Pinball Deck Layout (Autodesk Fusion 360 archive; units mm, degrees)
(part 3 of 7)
sketch "Posts Top" plane through (0, 0, 0) normal (0, 0, 1) x axis (1, 0, 0)
  line L1 (118.1698, 344.446) -> (150.6579, 255.1857)
  line L2 (143.7676, 248.9817) -> (113.9231, 263.5378)
  line L3 (108.8986, 346.3925) -> (111.7612, 347.4344)
  line L4 (106.0607, 276.0245) -> (105.6088, 341.6596)
  line L5 (250, 300) -> (250, 150)
  line L6 (250, 125) -> (250, 350)
  line L7 (391.1014, 346.3925) -> (388.2388, 347.4344)
  line L8 (393.9393, 276.0245) -> (394.3912, 341.6596)
  line L9 (381.8302, 344.446) -> (349.3421, 255.1857)
  line L10 (356.2324, 248.9817) -> (386.0769, 263.5378)
  circle C1 centre (112.8737, 341.4542) radius 2.25
  arc A1 centre (120.0603, 276.1209) radius 14 clockwise from (113.9231, 263.5378) to (106.0607, 276.0245)
  arc A2 centre (145.9594, 253.4756) radius 5 clockwise from (150.6579, 255.1857) to (143.7676, 248.9817)
  circle C2 centre (143.9975, 255.9422) radius 4
  circle C3 centre (113.492, 272.5077) radius 4
  circle C4 centre (113.492, 272.5077) radius 2.25
  circle C5 centre (112.8737, 341.4542) radius 4
  arc A3 centre (110.6087, 341.694) radius 5 clockwise from (105.6088, 341.6596) to (108.8986, 346.3925)
  arc A4 centre (113.4713, 342.7359) radius 5 clockwise from (111.7612, 347.4344) to (118.1698, 344.446)
  circle C6 centre (143.9975, 255.9422) radius 2.25
  circle C7 centre (386.508, 272.5077) radius 4
  arc A5 centre (389.3913, 341.694) radius 5 clockwise from (391.1014, 346.3925) to (394.3912, 341.6596)
  arc A6 centre (379.9397, 276.1209) radius 14 clockwise from (393.9393, 276.0245) to (386.0769, 263.5378)
  arc A7 centre (386.5287, 342.7359) radius 5 clockwise from (381.8302, 344.446) to (388.2388, 347.4344)
  circle C8 centre (387.1263, 341.4542) radius 4
  circle C9 centre (386.508, 272.5077) radius 2.25
  circle C10 centre (356.0025, 255.9422) radius 4
  circle C11 centre (387.1263, 341.4542) radius 2.25
  circle C12 centre (356.0025, 255.9422) radius 2.25
  arc A8 centre (354.0406, 253.4756) radius 5 clockwise from (356.2324, 248.9817) to (349.3421, 255.1857)
  point P3 (143.7676, 248.9817)
  point P25 (356.2324, 248.9817)
  point P5 (106.0607, 276.0245)
  point P26 (393.9393, 276.0245)
  point P6 (113.9231, 263.5378)
  point P28 (386.0769, 263.5378)
  point P11 (108.8986, 346.3925)
  point P29 (391.1014, 346.3925)
  point P12 (105.6088, 341.6596)
  point P27 (394.3912, 341.6596)
  point P16 (118.1698, 344.446)
  point P35 (381.8302, 344.446)
  point P18 (150.6579, 255.1857)
  point P40 (349.3421, 255.1857)
  point P19 (111.7612, 347.4344)
  point P37 (388.2388, 347.4344)
  perpendicular L1 L3
  tangent L1 A4
  tangent L3 A4
  tangent L3 A3
  tangent L4 A3
  concentric C3 C4
  concentric C1 C5
  tangent A1 L4
  tangent A1 L2
  tangent L2 A2
  tangent L1 A2
  parallel L5 L6
  symmetric P3 L6 P25
  symmetric P5 L6 P26
  symmetric P6 L6 P28
  symmetric P11 L6 P29
  symmetric P12 L6 P27
  symmetric P16 L6 P35
  symmetric P18 L6 P40
  symmetric P19 L6 P37
  symmetric C1 L6 C11
  symmetric A1 L6 A6
  symmetric A2 L6 A8
  symmetric C2 L6 C10
  symmetric C3 L6 C7
  symmetric C4 L6 C9
  symmetric C5 L6 C8
  symmetric A3 L6 A5
  symmetric A4 L6 A7
  symmetric C6 L6 C12
  dimension "d449" radius A4 = 5
  dimension "d450" radius A3 = 5
  dimension "d451" diameter C3 = 8
  dimension "d452" diameter C5 = 8
  dimension "d453" diameter C2 = 8
  dimension "d454" radius A1 = 14
  dimension "d455" radius A2 = 5
sketch "Right Launch Alley Wall" plane through (0, 0, 0) normal (0, 0, 1) x axis (1, 0, 0)
  line L1 (465, 200) -> (0.189, 200)
  line L2 (465, 200) -> (475.0152, 200)
  line L3 (465, 400) -> (465, 200.5)
  line L4 (475.0152, 200.5) -> (475.0152, 400)
  line L5 (475.0152, 200.5) -> (465, 200.5)
  line L6 (448.6603, 645) -> (465, 645)
  line L7 (464.7848, 721.9615) -> (443.8666, 651.4215)
  line L8 (475.0152, 400) -> (465, 400)
  line L9 (475, 400.5) -> (475, 423.4891)
  line L10 (465, 400.5) -> (475, 400.5)
  line L11 (465, 400.5) -> (465, 427.4801)
  line L12 (475, 532.1855) -> (465, 532.1855)
  line L13 (475, 531.6855) -> (465, 531.6855)
  line L14 (475, 531.6855) -> (475, 423.4891)
  line L15 (475, 721.9615) -> (475, 532.1855)
  line L16 (465, 531.6855) -> (465, 427.4801)
  line L17 (465, 645) -> (465, 532.1855)
  line L18 (464.7848, 721.9615) -> (475, 721.9615)
  line L19 (465, 723) -> (475, 723)
  line L20 (465, 750) -> (465, 723)
  line L21 (475, 750) -> (475, 723)
  line L22 (416.1118, 853.4419) -> (416.0548, 853.3004)
  line L23 (412.9292, 846.5912) -> (419.3573, 841.731)
  line L24 (419.0143, 854.221) -> (412.9292, 846.5912)
  circle C1 centre (470.0076, 235) radius 2.25
  circle C2 centre (470.0076, 235) radius 4
  circle C3 centre (470.0076, 350) radius 4
  circle C4 centre (470.0076, 350) radius 2.25
  circle C5 centre (470, 435) radius 4
  circle C6 centre (470, 435) radius 1.9
  circle C7 centre (470, 716) radius 1.9
  circle C8 centre (470, 716) radius 4
  circle C9 centre (470, 505) radius 1.9
  circle C10 centre (470, 505) radius 4
  circle C11 centre (450, 651) radius 1.9
  circle C12 centre (450, 651) radius 4
  arc A1 centre (448.6603, 650) radius 5 clockwise from (448.6603, 645) to (443.8666, 651.4215)
  circle C13 centre (470, 560) radius 1.9
  circle C14 centre (470, 560) radius 4
  arc A2 centre (350, 750) radius 150 clockwise from (350, 900) to (500, 750)
  arc A3 centre (350, 750) radius 125 clockwise from (419.0143, 854.221) to (475, 750)
  arc A4 centre (350, 750) radius 115 clockwise from (419.3573, 841.731) to (465, 750)
  circle C15 centre (422, 846) radius 1.9
  circle C16 centre (422, 846) radius 4
  circle C17 centre (470, 729) radius 1.9
  circle C18 centre (470, 729) radius 4
  circle C19 centre (450, 515) radius 2.25
  circle C20 centre (450, 515) radius 9
  point P2 (475.0152, 200)
  point P6 (475.0152, 200)
  point P3 (465, 200)
  point P7 (465, 200)
  point P34 (465, 532.1855)
  point P35 (475, 532.1855)
  point P42 (350, 750)
  point P43 (350, 750)
  point P45 (350, 750)
  coincident P2 P6
  coincident P3 P7
  perpendicular L1 L3
  perpendicular L2 L4
  concentric C1 C2
  concentric C3 C4
  perpendicular L4 L5
  vertical L16
  perpendicular L6 L16
  vertical L14
  concentric C5 C6
  concentric C7 C8
  concentric C9 C10
  concentric C11 C12
  tangent L6 A1
  tangent L7 A1
  perpendicular L8 L9
  perpendicular L9 L10
  coincident P34 L16
  perpendicular L12 L16
  coincident P35 L14
  collinear L14 L15
  collinear L16 L17
  concentric C13 C14
  coincident P42 P43
  coincident P42 P45
  perpendicular L15 L18
  horizontal L19
  tangent A4 L20
  tangent A3 L21
  concentric C15 C16
  concentric C17 C18
  tangent A4 L23
  concentric C19 C20
  dimension "d456" diameter C1 = 4.5
  dimension "d457" diameter C2 = 8
  dimension "d458" diameter C4 = 4.5
  dimension "d459" diameter C3 = 8
  dimension "d484" radius A1 = 5
extrude "Extrude76" new body sketch "Right Launch Alley Wall" profile of L2 L3 L4 C2 C3 along normal blind 25 bodies "Right Launch Runway"
extrude "Extrude77" add sketch "Right Launch Alley Wall" profile of C1 C2 C3 C4 along normal blind 4
fillet "Fillet24" radius 1
fillet "Fillet25" radius 2
extrude "Extrude78" new body sketch "Right Launch Alley Wall" profile of L17 L6 L7 L15 C5 C8 C10 C12 A1 along normal blind 25 bodies "Right Launch Runway Top"
extrude "Extrude80" new body sketch "Bottom Runways" along normal blind 25 bodies "Left Middle Runway"
extrude "Extrude81" add sketch "Bottom Runways" along normal blind 5
extrude "Extrude82" new body sketch "Bottom Runways" along normal blind 25 bodies "Left Upper Runway"
work_plane "WorkPlane7"
extrude "Extrude94" new body sketch "Bottom Runways" along normal blind 39
split "Split4"
remove_body "RemoveBody4"
extrude "Extrude95" add sketch "Bottom Runways" blind 3 from offset 36
work_plane "WorkPlane8"
split "Split5" bodies "Top Mid Right Overpass"
split "Split6"
remove_body "RemoveBody5"
extrude "Extrude96" add sketch "Bottom Runways" blind 14 from offset 25
extrude "Extrude97" add sketch "Bottom Runways" blind 14 from offset 25
sketch "Top Left Overpass" plane through (88.7119, 0, 0) normal (-1, 0, 0) x axis (0, -1, 0)
  line L1 (-844, 25) -> (-875, 25)
  line L2 (-844, 39) -> (-844, 25)
  line L3 (-875, 39) -> (-844, 39)
  line L4 (-875, 25) -> (-875, 39)
  line L5 (-875, 28) -> (-875, 25)
  line L6 (-844, 28) -> (-875, 28)
  line L7 (-844, 25) -> (-844, 28)
  line L8 (-875, 25) -> (-844, 25)
  point P2 (-875, 25)
  point P6 (-875, 25)
  point P7 (-875, 28)
  point P8 (-844, 28)
  point P3 (-844, 25)
  point P9 (-844, 25)
  coincident P2 P6
  coincident L4 P7
  coincident L2 P8
  perpendicular L2 L6
  coincident P3 P9
work_plane "WorkPlane9"
split "Split7"
remove_body "RemoveBody6"
extrude "Extrude98" new body sketch "Bottom Runways" along normal blind 28
work_plane "WorkPlane10"
split "Split8" bodies "Top Left Overpass"
remove_body "RemoveBody7"
extrude "Extrude99" cut sketch "Bottom Runways" along normal blind 50 bodies "Top Mid Left Overpass"
remove_body "RemoveBody8"
extrude "Extrude100" add sketch "Bottom Runways" along normal blind 55
extrude "Extrude101" cut sketch "Bottom Runways" along normal blind 60 bodies "Top Mid Right Overpass Ramp (1)"
work_plane "WorkPlane11" AlongDistance -16
split "Split9" bodies "Top Mid Right Overpass Ramp (1)"
remove_body "RemoveBody9"
remove_body "RemoveBody10"
fillet "Fillet36" radius 1.5
fillet "Fillet37" radius 20
extrude "Extrude102" add sketch "Bottom Runways" blind 30 from offset 25
work_plane "WorkPlane12" AlongDistance 15
split "Split10" bodies "Top Mid Right Overpass (1)", "Top Mid Right Overpass (2)"
remove_body "RemoveBody11"
remove_body "RemoveBody12"
split "Split11" bodies "Top Mid Right Overpass Ramp (2) (2)", "Top Mid Right Overpass Ramp (2) (1)"
remove_body "RemoveBody13"
remove_body "RemoveBody14"
extrude "Extrude103" cut sketch "Bottom Runways" along normal blind 60
extrude "Extrude104" add sketch "Bottom Runways" blind 30 from offset 25
split "Split12" bodies "Top Mid Left Overpass (1)", "Top Mid Left Overpass (2)"
remove_body "RemoveBody15"
remove_body "RemoveBody16"
extrude "Extrude105" new body sketch "Top Runways" along normal blind 25 bodies "Top Left Corner and ramp down"
combine "Combine6" bodies "Top Left Corner and ramp down"
extrude "Extrude106" add sketch "Top Runways" along normal blind 43
sketch "Left top corner construction lines" plane through (0.0081, 751.001, 0) normal (0, -1, 0) x axis (1, 0, 0)
  line L1 (96.4919, 0) -> (64.9919, 0)
  line L2 (96.4919, 25) -> (96.4919, 0)
  line L3 (96.4919, 43) -> (96.4919, 25)
  line L4 (64.9919, 43) -> (96.4919, 43)
  line L5 (64.9919, 0.298) -> (64.9919, 43)
  line L6 (64.9919, 0) -> (64.9919, 0.298)
  line L7 (95, 25) -> (64.9919, 25)
  horizontal L7
work_plane "WorkPlane13"
split "Split13" bodies "Top Left Overpass (1)", "Top Left Overpass (2)"
remove_body "RemoveBody17"
remove_body "RemoveBody18"
extrude "Extrude108" new body sketch "Bottom Runways" along normal blind 25 bodies "Left Target Framing"
extrude "Extrude110" add sketch "Bottom Runways" along normal blind 5
extrude "Extrude111" add sketch "Bottom Runways" along normal blind 5
fillet "Fillet49" radius 2
fillet "Fillet50" radius 2
fillet "Fillet51" radius 2
work_plane "WorkPlane14" AlongDistance 0.5
extrude "Extrude115" new body sketch "Bottom Runways" blind 3 from offset 25
fillet "Fillet52" radius 2
extrude "Extrude116" add sketch "Bottom Runways" blind 3 from offset 25 bodies "Left Target Framing"
fillet "Fillet53" radius 1.4
extrude "Extrude117" cut sketch "Bottom Runways" blind 40 from offset 5
extrude "Extrude118" cut sketch "Bottom Runways" blind 40 from offset 5
extrude "Extrude119" cut sketch "Top Runways" along normal blind 60
extrude "Extrude120" cut sketch "Top Runways" blind 60 from offset 5
extrude "Extrude121" cut sketch "Bottom Runways" along normal blind 80
fillet "Fillet55" radius 2
extrude "Extrude123" cut sketch "Bottom Runways" blind 80 from offset 5
extrude "Extrude124" new body sketch "Top Runways" along normal blind 24.8 bodies "Middle Ramp Stand"
extrude "Extrude125" add sketch "Top Runways" profile of L35 L36 L37 L38 L41 L42 L43 L44 L45 L46 along normal blind 51
extrude "Extrude126" add sketch "Top Runways" profile of L33 L34 L35 L36 L37 L38 L39 L40 L45 L46 L47 L48 L49 L50 blind 1.6 from offset 49.4
chamfer "Chamfer11" distance 0.8 distance 0.8
fillet "Fillet56" radius 1.5
extrude "Extrude127" add sketch "Top Runways" blind 9.8 from offset 15
extrude "Extrude128" new body sketch "Top Runways" blind 39 from offset 15
extrude "Extrude129" add sketch "Top Runways" blind 1.5 from offset 52.5
combine "Combine7"
extrude "Extrude130" add sketch "Top Runways" blind 20 from offset 15
chamfer "Chamfer12" distance 0.7
chamfer "Chamfer13" distance 10.3
chamfer "Chamfer14" distance 9 distance 2.7
chamfer "Chamfer15" distance 2.6
fillet "Fillet57" radius 2
extrude "Extrude131" new body sketch "Right Launch Alley Wall" profile of L17 L15 C5 C6 C9 C10 L9 L10 L11 L13 along normal blind 25 bodies "Right Mid Launch Runway"
fillet "Fillet58" radius 2
extrude "Extrude132" cut sketch "Right Launch Alley Wall" profile of C6 C9 along normal blind 40
extrude "Extrude133" cut sketch "Right Launch Alley Wall" profile of C5 C6 C9 C10 blind 40 from offset 5
extrude "Extrude134" cut sketch "Right Launch Alley Wall" profile of C13 along normal blind 40
extrude "Extrude135" cut sketch "Right Launch Alley Wall" profile of C13 C14 blind 40 from offset 5
extrude "Extrude136" add sketch "Right Launch Alley Wall" profile of C7 C8 C11 C12 along normal blind 5
extrude "Extrude137" cut sketch "Top Runways" along normal blind 100
extrude "Extrude138" cut sketch "Top Runways" blind 100 from offset 5
combine "Combine8" bodies "Left Upper Runway"
extrude "Extrude139" add sketch "Bottom Runways" along normal blind 5
extrude "Extrude140" new body sketch "Right Launch Alley Wall" profile of A3 A4 L19 L20 L21 C15 C16 C17 C18 along normal blind 25 bodies "Top Entry Runway"
fillet "Fillet59" radius 2
fillet "Fillet60" radius 3
extrude "Extrude142" cut sketch "Right Launch Alley Wall" profile of C15 C16 C17 C18 along normal blind 30
extrude "Extrude143" add sketch "Right Launch Alley Wall" profile of C15 C16 C17 C18 along normal blind 5
fillet "Fillet61" radius 0.4
extrude "Extrude144" cut sketch "Bottom Runways" along normal blind 80
extrude "Extrude145" add sketch "Bottom Runways" along normal blind 5
work_plane "WorkPlane15" AlongDistance 0.2
sketch "Ball Reload Positioner" plane through (0, 0, 25.2) normal (0, 0, 1) x axis (1, 0, 0)
  line L1 (465, 20) -> (499, 20)
  line L2 (465, 53) -> (465, 20)
  line L3 (465, 53) -> (499, 53)
  line L4 (499, 20) -> (499, 53)
  line L5 (496, 20) -> (496, 53)
  line L6 (475.3, 53) -> (475.3, 20)
  line L7 (478.3, 53) -> (478.3, 20)
  line L8
  line L9 (472, 25) -> (472, 45)
  circle C1 centre (470, 25) radius 1.2
  circle C2 centre (470, 45) radius 1.2
  circle C3 centre (470, 55) radius 1.2
  circle C4 centre (470, 35) radius 1.2
  arc A1 centre (470, 25) radius 2 clockwise from (472, 25) to (468, 25)
  arc A2 centre (470, 45) radius 2 clockwise from (468, 45) to (472, 45)
  circle C5 centre (470, 65) radius 1.2
  perpendicular L1 L2
  vertical L4
  vertical L5
  concentric C1 A1
  concentric C2 A2
  tangent L8 A2
  tangent L9 A1
  dimension "d919" diameter C5 = 2.4
  dimension "d920" diameter C3 = 2.4
  dimension "d921" diameter C2 = 2.4
  dimension "d922" diameter C4 = 2.4
  dimension "d923" diameter C1 = 2.4
extrude "Extrude146" new body sketch "Ball Reload Positioner" profile of L1 L2 L3 L4 L5 L6 L7 A1 A2 L8 L9 along normal blind 4 bodies "Ball Reload Positioner"
extrude "Extrude147" add sketch "Ball Reload Positioner" profile of L1 L3 L4 L5 L6 L7 against normal blind 20
fillet "Fillet62" radius 1
fillet "Fillet63" radius 1
extrude "Extrude148" cut sketch "Ball Reload Positioner" profile of C1 C2 C3 C4 C5 against normal blind 10
extrude "Extrude149" add sketch "Bottom Runways" blind 2 from offset 3.1
fillet "Fillet64" radius 0.8
fillet "Fillet65" radius 5
extrude "Extrude150" cut sketch "Top Runways" profile of L33 L34 L35 L36 L37 L38 L39 L40 L41 L42 L43 L44 L45 L46 L47 L48 L49 L50 L73 L74 along normal blind 22
fillet "Fillet66" radius 10
extrude "Extrude151" add sketch "Top Runways" profile of L45 L46 L47 L48 L49 L50 L73 L74 along normal blind 1
fillet "Fillet67" radius 9
fillet "Fillet68" radius 5
fillet "Fillet69" radius 1
sketch "Circuit" plane through (0, 0, 0) normal (0, 0, 1) x axis (1, 0, 0)
  line L1 (600, 1250) -> (0, 1250)
  line L2 (600, 1650) -> (600, 1250)
  line L3 (0, 1650) -> (600, 1650)
  line L4 (0, 1250) -> (0, 1650)
  line L5 (489.997, 2150.0002) -> (485, 2150.0002)
  line L6 (489.997, 2190.0002) -> (485, 2190.0002)
  line L7 (489.997, 2185.0213) -> (509.9119, 2194.9792)
  line L8 (489.997, 2180.0136) -> (509.9938, 2190.0123)
  line L9 (514.918, 2192.4745) -> (509.9938, 2190.0123)
  line L10 (514.918, 2192.4745) -> (514.9179, 2195)
  line L11 (514.9148, 2147.5359) -> (509.9973, 2149.9946)
  line L12 (514.9148, 2147.5359) -> (514.9149, 2145)
  line L13 (507.2404, 2156.0877) -> (505.3546, 2152.316)
  line L14 (503.3568, 2148.3108) -> (501.475, 2144.5472)
  line L15 (509.6966, 2150.145) -> (507.2404, 2156.0877)
  line L16 (507.6898, 2146.1444) -> (501.475, 2144.5472)
  line L17 (509.6966, 2150.145) -> (509.9973, 2149.9946)
  line L18 (489.997, 2159.9947) -> (505.3546, 2152.316)
  line L19 (507.6898, 2146.1444) -> (509.915, 2145.0319)
  line L20 (489.997, 2154.9903) -> (503.3568, 2148.3108)
  line L21 (489.997, 2154.9903) -> (489.997, 2150.0002)
  line L22 (489.997, 2180.0136) -> (489.997, 2159.9947)
  line L23 (514.9149, 2138.3888) -> (514.9149, 2145)
  line L24 (514.9149, 2120) -> (514.9149, 2132.9304)
  line L25 (509.915, 2136.4702) -> (509.915, 2145.0319)
  line L26 (509.915, 2120) -> (509.915, 2131.2814)
  line L27 (514.9127, 2201.6336) -> (514.9179, 2195)
  line L28 (514.8983, 2220.1069) -> (514.9084, 2207.0935)
  line L29 (509.9111, 2208.741) -> (509.9106, 2220.103)
  line L30 (509.9119, 2194.9792) -> (509.9114, 2203.5522)
  line L31 (489.997, 2185.0213) -> (489.997, 2190.0002)
  line L32 (465.0023, 2172.5088) -> (485, 2172.5089)
  line L33 (444.9979, 2172.5087) -> (459.9911, 2172.5088)
  line L34 (465.0026, 2167.5088) -> (485, 2167.5094)
  line L35 (444.9979, 2167.5083) -> (459.9914, 2167.5087)
  line L36 (485, 2167.5094) -> (485, 2150.0002)
  line L37 (485, 2190.0002) -> (485, 2172.5089)
  line L38 (235.0894, 1447.5) -> (255, 1447.5)
  line L39 (285, 1472.5) -> (280, 1470)
  line L40 (260.0001, 1460) -> (280, 1470)
  line L41 (260.0001, 1435) -> (273.3594, 1428.3203)
  line L42 (260.0001, 1470) -> (255, 1470)
  line L43 (280, 1400) -> (280, 1411.2702)
  line L44 (255, 1470) -> (255, 1452.5)
  line L45 (277.2435, 1436.0886) -> (275.3594, 1432.3203)
  line L46 (215, 1452.5) -> (230.0782, 1452.5)
  line L47 (285, 1400) -> (285, 1412.919)
  line L48 (273.3594, 1428.3203) -> (271.4753, 1424.5521)
  line L49 (280, 1488.7298) -> (280, 1500)
  line L50 (260.0001, 1460) -> (260.0001, 1440)
  line L51 (277.6975, 1426.1512) -> (280, 1425)
  line L52 (285, 1427.5) -> (280, 1430)
  line L53 (279.6975, 1430.1512) -> (280, 1430)
  line L54 (285, 1481.6228) -> (285, 1475)
  line L55 (215, 1452.5) -> (215, 1447.5)
  line L56 (215, 1447.5) -> (230.0782, 1447.5)
  line L57 (285, 1418.3772) -> (285, 1425)
  line L58 (255, 1447.5) -> (255, 1430)
  line L59 (260.0001, 1435) -> (260.0001, 1430)
  line L60 (260.0001, 1430) -> (255, 1430)
  line L61 (277.6975, 1426.1512) -> (271.4753, 1424.5521)
  line L62 (285, 1427.5) -> (285, 1425)
  line L63 (280, 1475) -> (280, 1483.541)
  line L64 (285, 1400) -> (280, 1400)
  line L65 (260.0001, 1465) -> (280, 1475)
  line L66 (280, 1500) -> (285, 1500)
  line L67 (285, 1500) -> (285, 1487.081)
  line L68 (279.6975, 1430.1512) -> (277.2435, 1436.0886)
  line L69 (280, 1416.459) -> (280, 1425)
  line L70 (235.0894, 1452.5) -> (255, 1452.5)
  line L71 (260.0001, 1465) -> (260.0001, 1470)
  line L72 (285, 1472.5) -> (285, 1475)
  line L73 (260.0001, 1440) -> (275.3594, 1432.3203)
  line L74 (435, 1481.6228) -> (435, 1475)
  line L75 (435, 1427.5) -> (435, 1425)
  line L76 (385.0894, 1452.5) -> (405, 1452.5)
  line L77 (410.0001, 1435) -> (423.3594, 1428.3203)
  line L78 (365, 1452.5) -> (380.0782, 1452.5)
  line L79 (410.0001, 1435) -> (410.0001, 1430)
  line L80 (385.0894, 1447.5) -> (405, 1447.5)
  line L81 (410.0001, 1465) -> (410.0001, 1470)
  line L82 (365, 1452.5) -> (365, 1447.5)
  line L83 (429.6975, 1430.1512) -> (430, 1430)
  line L84 (435, 1400) -> (435, 1412.919)
  line L85 (435, 1400) -> (430, 1400)
  line L86 (430, 1488.7298) -> (430, 1500)
  line L87 (427.6975, 1426.1512) -> (430, 1425)
  line L88 (430, 1500) -> (435, 1500)
  line L89 (435, 1418.3772) -> (435, 1425)
  line L90 (435, 1500) -> (435, 1487.081)
  line L91 (435, 1427.5) -> (430, 1430)
  line L92 (435, 1472.5) -> (435, 1475)
  line L93 (435, 1472.5) -> (430, 1470)
  line L94 (430, 1475) -> (430, 1483.541)
  line L95 (405, 1470) -> (405, 1452.5)
  line L96 (410.0001, 1430) -> (405, 1430)
  line L97 (430, 1400) -> (430, 1411.2702)
  line L98 (410.0001, 1470) -> (405, 1470)
  line L99 (430, 1416.459) -> (430, 1425)
  line L100 (410.0001, 1440) -> (425.3594, 1432.3203)
  line L101 (410.0001, 1460) -> (410.0001, 1440)
  line L102 (365, 1447.5) -> (380.0782, 1447.5)
  line L103 (405, 1447.5) -> (405, 1430)
  line L104 (430.6754, 1466.3573) -> (429.0832, 1469.5416)
  line L105 (427.8678, 1466.9616) -> (427.9382, 1467.1111)
  line L106 (427.0832, 1473.5416) -> (425.4911, 1476.7259)
  line L107 (423.5421, 1471.771) -> (425.4911, 1476.7259)
  line L108 (425.5421, 1467.771) -> (430.6754, 1466.3573)
  line L109 (429.0832, 1469.5416) -> (430, 1470)
  line L110 (410.0001, 1460) -> (425.5421, 1467.771)
  line L111 (427.0832, 1473.5416) -> (430, 1475)
  line L112 (410.0001, 1465) -> (423.5421, 1471.771)
  line L113 (429.6975, 1430.1512) -> (425.3594, 1432.3203)
  line L114 (427.6975, 1426.1512) -> (423.3594, 1428.3203)
  line L115 (165, 1554.162) -> (160, 1554.162)
  line L116 (160, 1554.162) -> (160, 1566.6482)
  line L117 (165, 1565.4321) -> (165, 1554.162)
  line L118 (175, 1575) -> (165, 1565.4321)
  line L119 (171.1459, 1577.3125) -> (165, 1571.4321)
  line L120 (160, 1566.6482) -> (165, 1571.4321)
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  point P20 (489.997, 2185.0213)
  point P28 (503.3568, 2148.3108)
  point P38 (514.9084, 2207.0935)
  point P41 (509.9114, 2203.5522)
  point P47 (459.9911, 2172.5088)
  point P48 (459.9914, 2167.5087)
  point P99 (260.0001, 1465)
  point P85 (273.3594, 1428.3203)
  point P93 (285, 1487.081)
  point P95 (280, 1483.541)
  point P83 (230.0782, 1452.5)
  point P80 (230.0782, 1447.5)
  point P125 (410.0001, 1465)
  point P146 (423.3594, 1428.3203)
  point P117 (435, 1487.081)
  point P128 (430, 1483.541)
  point P139 (380.0782, 1452.5)
  point P147 (380.0782, 1447.5)
  point P153 (427.9382, 1467.1111)
  point P418 (419.9999, 2300)
  point P522 (419.9999, 2300)
  point P242 (60, 2197.2708)
  point P956 (60, 2197.2708)
  point P470 (165, 2452.6226)
  point P958 (165, 2452.6226)
  point P448 (235, 2452.6226)
  point P959 (235, 2452.6226)
  point P496 (435, 2452.2708)
  point P960 (435, 2452.2708)
  point P239 (60, 2197.2708)
  point P981 (235, 2452.6226)
  point P982 (165, 2452.6226)
  point P1232 (1620, 2300)
  point P1564 (1620, 2300)
  point P1201 (1260, 2197.2708)
  point P1732 (1260, 2197.2708)
  point P1307 (1365, 2452.6226)
  point P1717 (1365, 2452.6226)
  point P1168 (1435, 2452.6226)
  point P1366 (1435, 2452.6226)
  point P1360 (1635, 2452.2708)
  point P1677 (1635, 2452.2708)
  point P1204 (1260, 2197.2708)
  point P1735 (1435, 2452.6226)
  point P1230 (1365, 2452.6226)
  horizontal L1
  perpendicular L1 L2
  perpendicular L2 L3
  perpendicular L1 L4
  vertical L36
  vertical L21
  perpendicular L5 L21
  perpendicular L6 L21
  vertical L25
  vertical L23
  coincident P20 L21
  parallel L8 L9
  parallel L11 L17
  coincident P28 L19
  perpendicular L13 L17
  collinear L17 L18
  collinear L19 L20
  collinear L21 L22
  collinear L23 L24
  collinear L25 L26
  coincident P38 L27
  coincident P41 L29
  collinear L27 L28
  collinear L29 L30
  coincident P47 L32
  coincident P48 L34
  collinear L32 L33
  collinear L34 L35
  collinear L36 L37
  vertical L58
  vertical L59
  perpendicular L59 L60
  perpendicular L42 L59
  vertical L69
  vertical L57
  perpendicular L57 L64
  perpendicular L54 L66
  coincident P99 L59
  parallel L39 L40
  parallel L52 L53
  coincident P85 L51
  perpendicular L45 L53
  collinear L53 L73
  collinear L41 L51
  collinear L50 L59
  collinear L47 L57
  collinear L43 L69
  coincident P93 L54
  coincident P95 L49
  collinear L54 L67
  collinear L49 L63
  perpendicular L55 L70
  coincident P83 L70
  coincident P80 L38
  collinear L46 L70
  collinear L38 L56
  collinear L44 L58
  vertical L103
  vertical L79
  perpendicular L79 L96
  perpendicular L79 L98
  vertical L99
  vertical L89
  perpendicular L85 L89
  perpendicular L74 L88
  coincident P125 L79
  parallel L93 L109
  parallel L83 L91
  coincident P146 L87
  collinear L83 L100
  collinear L77 L87
  collinear L79 L101
  collinear L84 L89
  collinear L97 L99
  coincident P117 L74
  coincident P128 L86
  collinear L74 L90
  collinear L86 L94
  perpendicular L76 L82
  coincident P139 L76
  coincident P147 L80
  collinear L76 L78
  collinear L80 L102
  collinear L95 L103
  perpendicular L104 L109
  coincident L108 P153
  collinear L109 L110
  collinear L111 L112
  parallel L119 L120
  coincident P418 P522
  coincident P242 P956
  coincident P470 P958
  coincident P448 P959
  coincident P496 P960
  coincident P239 P242
  coincident P448 P981
  coincident P470 P982
  coincident P1232 P1564
  coincident P1201 P1732
  coincident P1307 P1717
  coincident P1168 P1366
  coincident P1360 P1677
  coincident P1201 P1204
  coincident P1366 P1735
  coincident P1230 P1307
extrude "Extrude152" new body sketch "Circuit" along normal blind 1.4
move "Move12"
scale "Scale1" ScaleX 1.183 ScaleY 2.01
extrude "Extrude153" new body sketch "Circuit" along normal blind 1.4
extrude "Extrude156" new body sketch "Circuit" along normal blind 3 bodies "Strencil"
extrude "Extrude157" cut sketch "Circuit" along normal blind 10
copy_paste_bodies "CopyPasteBodies2"
move "Move13"
scale "Scale2" ScaleX 0.3 ScaleY 0.3
extrude "Extrude158" new body sketch "Circuit" along normal blind 1.5 bodies "Diode"
extrude "Extrude159" cut sketch "Circuit" along normal blind 10
extrude "Extrude160" new body sketch "Circuit" along normal blind 1.5 bodies "Transistor"
extrude "Extrude161" cut sketch "Circuit" along normal blind 10
copy_paste_bodies "CopyPasteBodies3"
move "Move14"
copy_paste_bodies "CopyPasteBodies4"
move "Move15"
move_face "MoveFace1"
move "Move16"
copy_paste_bodies "CopyPasteBodies5"
move "Move17"
scale "Scale3" ScaleX 1.8624 ScaleY 0.7705
move "Move18"
copy_paste_bodies "CopyPasteBodies6"
move "Move19"
scale "Scale4" ScaleX 2.5383
extrude "Extrude162" new body sketch "Circuit" along normal blind 1.5 bodies "Stripes"
extrude "Extrude163" cut sketch "Circuit" along normal blind 10
scale "Scale5" ScaleX 0.3 ScaleY 0.3
scale "Scale6" ScaleX 0.3 ScaleY 0.3
scale "Scale7" ScaleX 0.3 ScaleY 0.3
scale "Scale8" ScaleX 0.3 ScaleY 0.3
scale "Scale9" ScaleX 0.3 ScaleY 0.3
sketch "BackBox" plane through (0, 0, 0) normal (0, 0, 1) x axis (1, 0, 0)
  line L1 (2125, 2250) -> (2125, 1850)
  line L2 (2695, 2250) -> (2125, 2250)
  line L3 (2695, 1850) -> (2125, 1850)
  line L4 (2695, 2250) -> (2695, 1850)
  line L5 (2660, 1985) -> (2660, 1880)
  line L6 (2555, 1985) -> (2660, 1985)
  line L7 (2555, 1880) -> (2660, 1880)
  line L8 (2555, 1880) -> (2555, 1985)
  line L9 (2160, 1985) -> (2265, 1985)
  line L10 (2160, 1880) -> (2265, 1880)
  line L11 (2160, 1880) -> (2160, 1985)
  line L12 (2265, 1985) -> (2265, 1880)
  curve K1
  curve K2
  curve K3
  curve K4
  curve K5
  curve K6
  curve K7
  curve K8
  curve K9
  curve K10
  curve K11
  curve K12
  line L13 (2153.761, 2373.321) -> (2153.761, 2395.4463)
  line L14 (2395.0116, 2361.1258) -> (2166.2443, 2361.1258)
  line L15 (2410, 2401.3579) -> (2410, 2375.4976)
  line L16 (2179.9096, 2420.5192) -> (2390.8734, 2420.0432)
  line L17 (2156.1282, 2594.4925) -> (2156.1282, 2571.6762)
  line L18 (2387.8874, 2610) -> (2171.6929, 2610)
  line L19 (2400, 2581.5142) -> (2400, 2598.2002)
  line L20 (2166.9584, 2561.1258) -> (2379.5366, 2561.1258)
  line L21 (2235.3284, 2389.2708) -> (2232.7401, 2381.9877)
  line L22 (2239.6167, 2389.0222) -> (2235.3284, 2389.2708)
  line L23 (2236.6475, 2380.6675) -> (2239.6167, 2389.0222)
  line L24 (2232.7401, 2381.9877) -> (2236.6475, 2380.6675)
  line L25 (2358.5829, 2402.2185) -> (2347.2906, 2368.5152)
  line L26 (2362.6278, 2402.2185) -> (2358.5829, 2402.2185)
  line L27 (2351.4848, 2368.9608) -> (2362.6278, 2402.2185)
  line L28 (2347.2906, 2368.5152) -> (2351.4848, 2368.9608)
  line L29 (2188.4386, 2605.0237) -> (2177, 2571)
  line L30 (2190.3905, 2605.0237) -> (2188.4386, 2605.0237)
  line L31 (2178.6002, 2570.8889) -> (2190.3905, 2605.0237)
  line L32 (2177, 2571) -> (2178.6002, 2570.8889)
  line L33 (2222.4117, 2592.8043) -> (2218.9671, 2582.3845)
  line L34 (2219.2911, 2592.8043) -> (2222.4117, 2592.8043)
  line L35 (2215.9278, 2582.6302) -> (2219.2911, 2592.8043)
  line L36 (2215.9278, 2582.6302) -> (2218.9671, 2582.3845)
  line L37 (2305, 2601) -> (2301.1326, 2590.6136)
  line L38 (2302, 2601) -> (2305, 2601)
  line L39 (2298.1676, 2590.7075) -> (2302, 2601)
  line L40 (2301.1326, 2590.6136) -> (2298.1676, 2590.7075)
  line L41 (2400, 2598.2002) -> (2387.8874, 2610)
  line L42 (2400, 2581.5142) -> (2379.5366, 2561.1258)
  line L43 (2166.9584, 2561.1258) -> (2156.1282, 2571.6762)
  line L44 (2171.6929, 2610) -> (2156.1282, 2594.4925)
  line L45 (2179.9096, 2420.5192) -> (2153.761, 2395.4463)
  line L46 (2410, 2375.4976) -> (2395.0116, 2361.1258)
  line L47 (2390.8734, 2420.0432) -> (2410, 2401.3579)
  line L48 (2153.761, 2373.321) -> (2166.2443, 2361.1258)
  line L49 (2458.2178, 1957.818) -> (2457.71, 1957.818)
  line L50 (2457.9639, 1957.818) -> (2458.2178, 1957.818)
  line L51 (2457.9639, 1959.3415) -> (2457.9639, 1957.818)
  line L52 (2457.71, 1959.0876) -> (2457.9639, 1959.3415)
  line L53 (2399.798, 1979.6615) -> (2399.798, 1978.138)
  line L54 (2400.8137, 1978.138) -> (2399.798, 1979.6615)
  line L55 (2400.8137, 1979.6615) -> (2400.8137, 1978.138)
  line L56 (2402.0833, 1978.138) -> (2401.5754, 1978.138)
  line L57 (2402.3372, 1978.3919) -> (2402.0833, 1978.138)
  line L58 (2402.3372, 1978.8998) -> (2402.3372, 1978.3919)
  line L59 (2402.0833, 1979.1537) -> (2402.3372, 1978.8998)
  line L60 (2401.5754, 1979.1537) -> (2402.0833, 1979.1537)
  line L61 (2401.3215, 1978.8998) -> (2401.5754, 1979.1537)
  line L62 (2401.3215, 1978.3919) -> (2401.3215, 1978.8998)
  line L63 (2401.5754, 1978.138) -> (2401.3215, 1978.3919)
  line L64 (2403.3528, 1978.138) -> (2402.845, 1979.1537)
  line L65 (2403.8607, 1979.1537) -> (2403.3528, 1978.138)
  line L66 (2405.892, 1978.138) -> (2406.9077, 1978.138)
  line L67 (2406.9077, 1979.1537) -> (2405.892, 1978.138)
  line L68 (2406.9077, 1979.4076) -> (2406.9077, 1979.1537)
  line L69 (2406.6538, 1979.6615) -> (2406.9077, 1979.4076)
  line L70 (2406.1459, 1979.6615) -> (2406.6538, 1979.6615)
  line L71 (2405.892, 1979.4076) -> (2406.1459, 1979.6615)
  line L72 (2407.6695, 1979.6615) -> (2407.4155, 1979.4076)
  line L73 (2408.1773, 1979.6615) -> (2407.6695, 1979.6615)
  line L74 (2408.4312, 1979.4076) -> (2408.1773, 1979.6615)
  line L75 (2408.4312, 1978.3919) -> (2408.4312, 1979.4076)
  line L76 (2408.1773, 1978.138) -> (2408.4312, 1978.3919)
  line L77 (2407.6695, 1978.138) -> (2408.1773, 1978.138)
  line L78 (2407.4155, 1978.3919) -> (2407.6695, 1978.138)
  line L79 (2407.4155, 1979.4076) -> (2407.4155, 1978.3919)
  line L80 (2408.939, 1978.138) -> (2409.9547, 1978.138)
  line L81 (2409.9547, 1979.1537) -> (2408.939, 1978.138)
  line L82 (2409.9547, 1979.4076) -> (2409.9547, 1979.1537)
  line L83 (2409.7008, 1979.6615) -> (2409.9547, 1979.4076)
  line L84 (2409.193, 1979.6615) -> (2409.7008, 1979.6615)
  line L85 (2408.939, 1979.4076) -> (2409.193, 1979.6615)
  line L86 (2410.4626, 1979.6615) -> (2411.4782, 1979.6615)
  line L87 (2410.4626, 1978.8998) -> (2410.4626, 1979.6615)
  line L88 (2410.9704, 1979.1537) -> (2410.4626, 1978.8998)
  line L89 (2411.2243, 1979.1537) -> (2410.9704, 1979.1537)
  line L90 (2411.4782, 1978.8998) -> (2411.2243, 1979.1537)
  line L91 (2411.4782, 1978.3919) -> (2411.4782, 1978.8998)
  line L92 (2411.2243, 1978.138) -> (2411.4782, 1978.3919)
  line L93 (2410.7165, 1978.138) -> (2411.2243, 1978.138)
  line L94 (2410.4626, 1978.3919) -> (2410.7165, 1978.138)
  line L95 (2414.5252, 1979.6615) -> (2413.5096, 1979.6615)
  line L96 (2414.0174, 1979.6615) -> (2414.5252, 1979.6615)
  line L97 (2414.0174, 1978.138) -> (2414.0174, 1979.6615)
  line L98 (2415.7948, 1979.6615) -> (2416.0487, 1979.4076)
  line L99 (2415.287, 1979.6615) -> (2415.7948, 1979.6615)
  line L100 (2415.0331, 1979.4076) -> (2415.287, 1979.6615)
  line L101 (2415.0331, 1978.3919) -> (2415.0331, 1979.4076)
  line L102 (2415.287, 1978.138) -> (2415.0331, 1978.3919)
  line L103 (2415.7948, 1978.138) -> (2415.287, 1978.138)
  line L104 (2416.0487, 1978.3919) -> (2415.7948, 1978.138)
  line L105 (2416.0487, 1978.8998) -> (2416.0487, 1978.3919)
  line L106 (2415.5409, 1978.8998) -> (2416.0487, 1978.8998)
  line L107 (2416.5566, 1979.6615) -> (2416.5566, 1978.138)
  line L108 (2417.0644, 1979.1537) -> (2416.5566, 1979.6615)
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  point P33 (2188.4386, 2605.0237)
  point P34 (2190.3905, 2605.0237)
  vertical L1
  perpendicular L1 L2
  perpendicular L1 L3
  perpendicular L2 L4
  perpendicular L5 L6
  perpendicular L5 L7
  perpendicular L7 L8
  perpendicular L9 L12
  perpendicular L10 L12
  perpendicular L10 L11
  perpendicular K7 L13
  perpendicular K8 L14
  perpendicular K7 L15
  perpendicular K11 L17
  perpendicular K12 L18
  perpendicular K11 L19
  perpendicular L17 L20
  parallel L21 L23
  horizontal L26
  parallel L25 L27
  coincident K11 P33
  coincident K11 P34
  horizontal L34
  parallel L33 L35
  horizontal L38
  parallel L37 L39
  dimension "d1005" Text1-Height = 33
  dimension "d1007" Text2-Height = 33
  dimension "d1009" Text3-Height = 33
  dimension "d1078" Text4-Height = 18
  dimension "d1080" Text5-Height = 18
  dimension "d1318" Text6-Height = 18
  dimension "d1320" Text7-Height = 18
  dimension "d1322" Text8-Height = 18
  dimension "d1324" Text9-Height = 18
  dimension "d1326" Text10-Height = 18
sketch "Score and Player Bezels" plane through (0, 0, 0) normal (0, 0, 1) x axis (1, 0, 0)
  line L1 (2398.274, 1976.09) -> (2512.574, 1976.09)
  line L2 (2397.274, 1957.31) -> (2397.274, 1975.08)
  line L3 (2512.574, 1956.31) -> (2398.274, 1956.31)
  line L4 (2513.574, 1975.09) -> (2513.574, 1957.31)
  line L5 (2397.274, 1976.09) -> (2397.274, 1975.08)
  line L6 (2397.274, 1976.09) -> (2398.274, 1976.09)
  line L7 (2397.274, 1956.2873) -> (2397.274, 1957.31)
  line L8 (2513.574, 1976.09) -> (2513.574, 1975.09)
  line L9 (2513.574, 1976.09) -> (2512.574, 1976.09)
  line L10 (2513.574, 1956.31) -> (2512.574, 1956.31)
  line L11 (2513.574, 1956.31) -> (2513.574, 1957.31)
  line L12 (2515.974, 1975.09) -> (2515.974, 1957.31)
  line L13 (2398.274, 1978.49) -> (2512.574, 1978.49)
  line L14 (2512.574, 1953.91) -> (2398.274, 1953.91)
  line L15 (2394.874, 1957.31) -> (2394.874, 1975.08)
  line L16 (2389.874, 1957.31) -> (2389.874, 1975.08)
  line L17 (2398.274, 1983.49) -> (2512.574, 1983.49)
  line L18 (2506.497, 1948.91) -> (2398.274, 1948.91)
  line L19 (2520.974, 1975.09) -> (2520.974, 1957.3097)
  line L20 (2516.0924, 1978.49) -> (2512.574, 1978.49)
  line L21 (2520.974, 1983.49) -> (2512.574, 1983.49)
  line L22 (2520.974, 1975.09) -> (2520.974, 1983.49)
  line L23 (2515.974, 1953.91) -> (2512.574, 1953.91)
  line L24 (2520.974, 1949) -> (2506.497, 1948.91)
  line L25 (2515.974, 1953.91) -> (2515.974, 1957.31)
  line L26 (2520.974, 1949) -> (2520.974, 1957.3097)
  line L27 (2389.874, 1983.49) -> (2389.874, 1975.08)
  line L28 (2394.874, 1978.49) -> (2394.874, 1975.08)
  line L29 (2394.874, 1978.49) -> (2398.274, 1978.49)
  line L30 (2397.5, 1978.49) -> (2394.874, 1978.49)
  line L31 (2389.874, 1983.49) -> (2398.274, 1983.49)
  line L32 (2394.874, 1953.91) -> (2394.874, 1957.31)
  line L33 (2389.874, 1948.91) -> (2389.874, 1957.31)
  line L34 (2394.874, 1953.91) -> (2398.274, 1953.91)
  line L35 (2389.874, 1948.91) -> (2398.274, 1948.91)
  line L36 (2389.874, 1888.91) -> (2389.874, 1897.31)
  line L37 (2414.974, 1915.09) -> (2414.974, 1897.31)
  line L38 (2394.874, 1893.91) -> (2394.874, 1897.31)
  line L39 (2389.874, 1923.49) -> (2398.274, 1923.49)
  line L40 (2412.574, 1896.31) -> (2412.574, 1897.31)
  line L41 (2394.874, 1918.49) -> (2394.874, 1915.08)
  line L42 (2397.274, 1916.09) -> (2397.274, 1915.08)
  line L43 (2419.974, 1915.09) -> (2419.974, 1923.49)
  line L44 (2412.574, 1916.09) -> (2412.574, 1915.09)
  line L45 (2389.874, 1888.91) -> (2398.274, 1888.91)
  line L46 (2394.874, 1918.49) -> (2398.274, 1918.49)
  line L47 (2414.974, 1893.91) -> (2414.974, 1897.31)
  line L48 (2389.874, 1923.49) -> (2389.874, 1915.08)
  line L49 (2397.5, 1918.49) -> (2394.874, 1918.49)
  line L50 (2397.274, 1916.09) -> (2398.274, 1916.09)
  line L51 (2419.974, 1915.09) -> (2419.974, 1897.3097)
  line L52 (2394.874, 1897.31) -> (2394.874, 1915.08)
  line L53 (2414.974, 1893.91) -> (2398.274, 1893.91)
  line L54 (2398.274, 1923.49) -> (2419.974, 1923.49)
  line L55 (2398.274, 1918.49) -> (2414.974, 1918.49)
  line L56 (2412.574, 1896.31) -> (2398.274, 1896.31)
  line L57 (2419.974, 1889) -> (2419.974, 1897.3097)
  line L58 (2389.874, 1897.31) -> (2389.874, 1915.08)
  line L59 (2394.874, 1893.91) -> (2398.274, 1893.91)
  line L60 (2412.574, 1915.09) -> (2412.574, 1897.31)
  line L61 (2397.274, 1897.31) -> (2397.274, 1915.08)
  line L62 (2398.274, 1916.09) -> (2412.574, 1916.09)
  line L63 (2397.274, 1896.2873) -> (2397.274, 1897.31)
  line L64 (2414.974, 1918.49) -> (2414.974, 1915.09)
  arc A1 centre (2398.274, 1934.3192) radius 21.9908 clockwise from (2397.274, 1956.2873) to (2398.274, 1956.31)
  arc A2 centre (2564.8458, 1975.09) radius 48.8718 clockwise from (2515.974, 1975.09) to (2516.0924, 1978.49)
  arc A3 centre (2398.274, 1874.3192) radius 21.9908 clockwise from (2397.274, 1896.2873) to (2398.274, 1896.31)
  arc A4 centre (2398.274, 4504.1667) radius 2615.2567 clockwise from (2419.974, 1889) to (2398.274, 1888.91)
  point P36 (2397.5, 1978.49)
  point P51 (2397.5, 1918.49)
  perpendicular L5 L6
  parallel L2 L7
  tangent L3 A1
  perpendicular L8 L9
  parallel L3 L10
  perpendicular L10 L11
  parallel L13 L20
  tangent L12 A2
  perpendicular L21 L22
  parallel L14 L23
  parallel L19 L26
  parallel L16 L27
  parallel L15 L28
  perpendicular L28 L29
  coincident L29 P36
  perpendicular L27 L31
  parallel L16 L33
  perpendicular L33 L35
  perpendicular L42 L50
  parallel L61 L63
  tangent A3 L56
  parallel L51 L57
  parallel L48 L58
  parallel L41 L52
  perpendicular L41 L46
  coincident P51 L46
  perpendicular L39 L48
  parallel L36 L58
  perpendicular L36 L45
  tangent L45 A4
extrude "Extrude180" new body sketch "Score and Player Bezels" profile of L1 L2 L3 L4 L5 L6 L7 A1 L8 L9 L10 L11 L12 L13 L14 L15 L20 A2 L23 L25 L28 L29 L30 L32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 along normal blind 9 bodies "Score Bezel"
extrude "Extrude181" add sketch "Score and Player Bezels" profile of L12 L13 L14 L15 L16 L17 L18 L19 L20 L21 A2 L22 L23 L24 L25 L26 L27 L28 L29 L30 L31 L32 L33 L34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 along normal blind 1.6
chamfer "Chamfer17" distance 0.8 distance 1.2
extrude "Extrude182" new body sketch "Score and Player Bezels" profile of A3 L37 L38 L40 L41 L42 L44 L46 L47 L49 L50 L52 L53 L55 L56 L59 L60 L61 L62 L63 L64 along normal blind 9 bodies "Player Bezel"
extrude "Extrude183" add sketch "Score and Player Bezels" profile of L36 L37 L38 L39 L41 L43 L45 L46 L47 L48 L49 L51 L52 L53 L54 L55 L57 L58 L59 L64 A4 along normal blind 1.6
chamfer "Chamfer18" distance 0.8 distance 1.2
extrude "Extrude164" new body sketch "BackBox" profile of L13 L14 L15 L16 along normal blind 1.5 bodies "Backbox Electron"
extrude "Extrude165" cut sketch "BackBox" along normal blind 10 bodies "Backbox Electron (1)", "Backbox Electron (2)"
extrude "Extrude166" add sketch "BackBox" profile of L21 L22 L23 L24 L25 L26 L27 L28 along normal blind 1.5 bodies "Backbox Electron (1)", "Backbox Electron (2)"
extrude "Extrude167" new body sketch "BackBox" profile of L17 L18 L19 L20 L29 L30 L31 L32 L33 L34 L35 L36 L37 L38 L39 L40 along normal blind 1.5 bodies "Backbox Bandit"
extrude "Extrude168" cut sketch "BackBox" along normal blind 10 bodies "Backbox Bandit (1)", "Backbox Bandit (2)", "Backbox Bandit (3)"
extrude "Extrude169" add sketch "BackBox" profile of L29 L30 L31 L32 L33 L34 L35 L36 L37 L38 L39 L40 along normal blind 1.5 bodies "Backbox Bandit (1)", "Backbox Bandit (2)", "Backbox Bandit (3)"
sketch "Silicon Chip" plane through (0, 0, 0) normal (0, 0, 1) x axis (1, 0, 0)
  line L1 (2213.5462, 2093.7135) -> (2213.5913, 2094.6519)
  line L2 (2187.0252, 2026.9317) -> (2187.2404, 2029.7685)
  line L3 (2221.4721, 2093.8439) -> (2212.7481, 2095.5264)
  line L4 (2206.6772, 2067.8086) -> (2222.765, 2064.7062)
  line L5 (2225.7761, 2051.4373) -> (2226.0348, 2051.3865)
  line L6 (2220.9782, 2093.2549) -> (2220.9782, 2092.3136)
  line L7 (2238.8531, 2087.183) -> (2238.8531, 2082.7185)
  line L8 (2192.2849, 2026.5268) -> (2190.2857, 2026.9173)
  line L9 (2206.7014, 2063.3216) -> (2206.6772, 2067.8086)
  line L10 (2232.2674, 2053.9124) -> (2225.8242, 2055.1514)
  line L11 (2234.5491, 2088.7065) -> (2229.0457, 2089.7752)
  line L12 (2223.9339, 2102.6321) -> (2217.6819, 2103.847)
  line L13 (2205.8319, 2081.2243) -> (2205.8319, 2076.0697)
  line L14 (2168.5875, 2023.9008) -> (2171.1196, 2020.3151)
  line L15 (2229.0457, 2089.7752) -> (2228.6929, 2089.8475)
  line L16 (2206.7258, 2080.3676) -> (2222.8129, 2077.2611)
  line L17 (2206.7013, 2050.6163) -> (2206.7628, 2055.0785)
  line L18 (2177.8206, 2041.9552) -> (2171.2224, 2043.1679)
  line L19 (2222.8129, 2077.2611) -> (2238.8528, 2074.1546)
  line L20 (2238.7576, 2052.6735) -> (2232.2674, 2053.9124)
  line L21 (2233.3728, 2088.2433) -> (2238.8531, 2087.183)
  line L22 (2238.7811, 2078.2541) -> (2207.0317, 2084.3811)
  line L23 (2232.5496, 2050.1234) -> (2238.8057, 2048.9111)
  line L24 (2239.5348, 2077.4086) -> (2239.5352, 2077.4086)
  line L25 (2212.6995, 2093.8894) -> (2212.6995, 2092.2525)
  line L26 (2166.1316, 2027.45) -> (2168.5875, 2023.9008)
  line L27 (2206.1847, 2083.8691) -> (2222.9538, 2080.6202)
  line L28 (2228.6929, 2089.8475) -> (2228.6881, 2092.6323)
  line L29 (2238.8299, 2044.4518) -> (2238.7359, 2039.994)
  line L30 (2238.8057, 2048.9111) -> (2238.8299, 2044.4518)
  line L31 (2227.8458, 2092.2874) -> (2227.8929, 2089.3035)
  line L32 (2238.8528, 2057.1387) -> (2238.7576, 2052.6735)
  line L33 (2226.4183, 2066.9158) -> (2239.5819, 2064.3715)
  line L34 (2206.6786, 2075.8928) -> (2206.7258, 2080.3676)
  line L35 (2205.8357, 2091.7219) -> (2205.8319, 2083.9455)
  line L36 (2211.1762, 2105.0677) -> (2210.5538, 2104.6234)
  line L37 (2166.1316, 2032.3498) -> (2166.1316, 2027.45)
  line L38 (2206.7628, 2055.0785) -> (2219.5921, 2052.6286)
  line L39 (2171.2224, 2043.1679) -> (2168.6365, 2040.1894)
  line L40 (2178.1734, 2036.7186) -> (2178.1734, 2041.8817)
  line L41 (2239.3467, 2074.7502) -> (2209.007, 2080.6136)
  line L42 (2217.1672, 2092.0738) -> (2213.5462, 2092.7752)
  line L43 (2223.3252, 2102.0741) -> (2225.562, 2098.6727)
  line L44 (2225.562, 2098.6727) -> (2227.7988, 2095.2713)
  line L45 (2178.1734, 2041.8817) -> (2177.8206, 2041.9552)
  line L46 (2166.1316, 2037.2496) -> (2166.1316, 2032.3498)
  line L47 (2212.7481, 2095.5264) -> (2212.6995, 2093.8894)
  line L48 (2206.6786, 2071.418) -> (2206.6786, 2075.8928)
  line L49 (2239.6995, 2074.6774) -> (2239.3467, 2074.7502)
  line L50 (2227.8929, 2089.3035) -> (2233.3728, 2088.2433)
  line L51 (2206.679, 2084.4544) -> (2206.6811, 2091.8671)
  line L52 (2188.1246, 2027.3096) -> (2188.0201, 2022.1918)
  line L53 (2213.0523, 2092.1803) -> (2221.7763, 2090.4978)
  line L54 (2192.1202, 2028.8706) -> (2192.2849, 2027.6795)
  line L55 (2239.6759, 2078.1266) -> (2239.6998, 2082.5399)
  line L56 (2213.2169, 2057.59) -> (2206.7256, 2058.8346)
  line L57 (2239.6998, 2082.5399) -> (2239.6998, 2087.7102)
  line L58 (2238.8528, 2061.6038) -> (2238.8528, 2057.1387)
  line L59 (2205.8319, 2070.915) -> (2209.6021, 2070.1712)
  line L60 (2227.7988, 2095.2713) -> (2227.8458, 2092.2874)
  line L61 (2184.4109, 2021.3574) -> (2186.8382, 2024.1167)
  line L62 (2181.6889, 2018.2504) -> (2181.8362, 2018.4243)
  line L63 (2217.3073, 2093.9534) -> (2220.9782, 2093.2549)
  line L64 (2239.5819, 2064.3715) -> (2239.6995, 2069.508)
  line L65 (2208.9268, 2101.7447) -> (2211.2692, 2104.2863)
  line L66 (2181.8362, 2018.4243) -> (2184.4109, 2021.3574)
  line L67 (2172.9992, 2031.3956) -> (2172.9992, 2029.5764)
  line L68 (2173.0967, 2033.2147) -> (2172.9992, 2031.3956)
  line L69 (2184.7587, 2039.914) -> (2189.6916, 2038.9849)
  line L70 (2190.2857, 2026.9173) -> (2188.1246, 2027.3096)
  line L71 (2178.9895, 2032.5197) -> (2178.7716, 2029.6364)
  line L72 (2199.9832, 2021.0804) -> (2199.9905, 2026.2912)
  line L73 (2190.8972, 2026.1024) -> (2193.014, 2025.7101)
  line L74 (2194.4833, 2038.0545) -> (2196.8179, 2034.6809)
  line L75 (2168.6365, 2040.1894) -> (2166.1316, 2037.2496)
  line L76 (2174.2692, 2041.9565) -> (2177.115, 2041.4137)
  line L77 (2178.1734, 2031.5554) -> (2178.1734, 2036.7186)
  line L78 (2171.1196, 2020.3151) -> (2176.4423, 2019.2645)
  line L79 (2213.5913, 2094.6519) -> (2217.3073, 2093.9534)
  line L80 (2181.3271, 2019.019) -> (2176.4751, 2019.9333)
  line L81 (2186.404, 2030.5655) -> (2186.1764, 2027.4038)
  line L82 (2176.4751, 2019.9333) -> (2171.6474, 2020.8684)
  line L83 (2194.89, 2015.7499) -> (2197.4571, 2018.431)
  line L84 (2239.5352, 2077.4086) -> (2239.6759, 2078.1266)
  line L85 (2186.1764, 2027.4038) -> (2185.9837, 2024.3257)
  line L86 (2173.8458, 2030.0991) -> (2173.8458, 2031.2197)
  line L87 (2166.9783, 2032.3473) -> (2166.9783, 2037.0788)
  line L88 (2179.152, 2034.9221) -> (2178.9895, 2032.5197)
  line L89 (2182.3081, 2037.3107) -> (2184.7587, 2039.914)
  line L90 (2212.6995, 2092.2525) -> (2213.0523, 2092.1803)
  line L91 (2238.8531, 2082.7185) -> (2238.7811, 2078.2541)
  line L92 (2220.9782, 2092.3136) -> (2220.8833, 2091.3723)
  line L93 (2193.014, 2025.7101) -> (2193.1316, 2027.5274)
  line L94 (2188.8981, 2026.4929) -> (2190.8972, 2026.1024)
  line L95 (2188.8981, 2022.0221) -> (2188.8981, 2026.4929)
  line L96 (2192.7788, 2029.4187) -> (2186.404, 2030.5655)
  line L97 (2199.1525, 2021.3546) -> (2196.8888, 2018.9582)
  line L98 (2199.1525, 2026.3309) -> (2199.1525, 2021.3546)
  line L99 (2178.7163, 2029.1554) -> (2176.2811, 2029.6273)
  line L100 (2217.3466, 2103.2185) -> (2223.3252, 2102.0741)
  line L101 (2213.5462, 2092.7752) -> (2213.5462, 2093.7135)
  line L102 (2176.4423, 2019.2645) -> (2181.6889, 2018.2504)
  line L103 (2197.4571, 2018.431) -> (2199.9832, 2021.0804)
  line L104 (2183.6675, 2021.6827) -> (2181.3271, 2019.019)
  line L105 (2221.7763, 2090.4978) -> (2221.8249, 2092.1347)
  line L106 (2179.7825, 2031.5385) -> (2179.9985, 2034.7088)
  line L107 (2185.9837, 2024.3257) -> (2183.6675, 2021.6827)
  line L108 (2193.1316, 2029.3465) -> (2192.7788, 2029.4187)
  line L109 (2192.2849, 2027.6795) -> (2192.2849, 2026.5268)
  line L110 (2211.2692, 2104.2863) -> (2217.3466, 2103.2185)
  line L111 (2188.1056, 2017.0462) -> (2194.89, 2015.7499)
  line L112 (2221.8249, 2093.7717) -> (2221.4721, 2093.8439)
  line L113 (2186.8382, 2024.1167) -> (2187.0252, 2026.9317)
  line L114 (2206.6832, 2099.2797) -> (2208.9268, 2101.7447)
  line L115 (2220.8833, 2091.3723) -> (2217.1672, 2092.0738)
  line L116 (2187.2404, 2029.7685) -> (2192.1202, 2028.8706)
  line L117 (2179.9985, 2034.7088) -> (2182.3081, 2037.3107)
  line L118 (2188.0201, 2022.1918) -> (2188.1056, 2017.0462)
  line L119 (2176.1742, 2031.9459) -> (2178.1734, 2031.5554)
  line L120 (2177.162, 2032.4415) -> (2173.0967, 2033.2147)
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scale "Scale10" ScaleFactor 2
scale "Scale11" ScaleFactor 0.8
extrude "Extrude170" new body sketch "Silicon Chip" along normal blind 1.4 bodies "Silicon Chip Logo BACKGRUOND"
extrude "Extrude171" cut sketch "Silicon Chip" along normal blind 10
extrude "Extrude172" new body sketch "Silicon Chip" along normal blind 1.4 bodies "Silicon Chip Logo OutLines"
extrude "Extrude173" cut sketch "Silicon Chip" along normal blind 10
